(* Logix 5000 project; controller Test vendor 1 type 14 code 92 rev 33.11; software revision 33.00; part 4 of 4 *)
(* tags used below, declared in another part *)
   WLS : Banner_WLS_v4;
   Port_Data : Banner_IOL_Port_v4;
   Port : INT;   // Port Number that device is plugged into.
   Local_Control : DINT;
   Command_Being_Processed : BOOL;
   Update_Archive : BOOL;
   Index_Write_Inprocess : DINT;
   Inprocess_Index : DINT;
   GW_Index : DINT;
(* Banner_WLS_Param_v4, continued *)

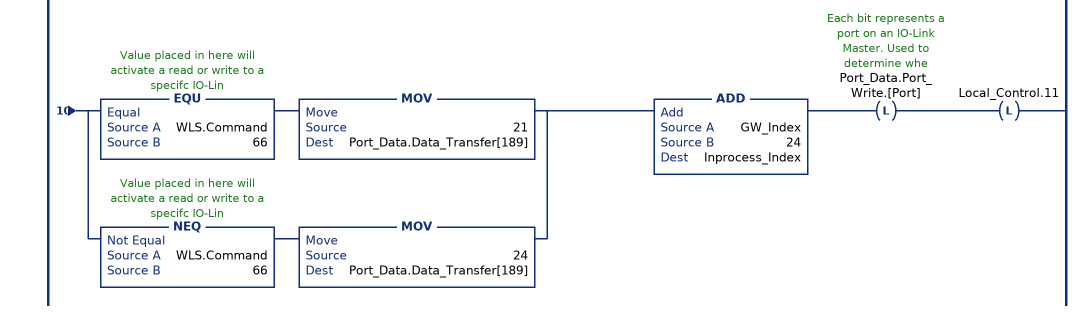
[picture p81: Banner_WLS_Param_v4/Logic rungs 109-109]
   // *****************************************************************************************************************************************************************************
   // Section of AOI that controls writing of the Gauge Mode Center Settings parameters (index 86), Gauge Mode Threshold 1 & 2 Settings (Index 87 &88).
   // *****************************************************************************************************************************************************************************
   109: XIO(Command_Being_Processed)XIO(Local_Control.11)GEQ(WLS.Command,66)LEQ(WLS.Command,68)SUB(WLS.Command,66,GW_Index)OTL(Command_Being_Processed)BTD(WLS.Write.G_Config.CC[GW_Index].Back_CC.Direction,0,Port_Data.Data_Transfer[0],0,8)BTD(WLS.Write.G_Config.CC[GW_Index].Back_CC.Percent_Width_C1,0,Port_Data.Data_Transfer[1],0,8)BTD(WLS.Write.G_Config.CC[GW_Index].Back_CC.ScrollBounce,0,Port_Data.Data_Transfer[2],0,8)BTD(WLS.Write.G_Config.CC[GW_Index].Back_CC.Color_2_Intensity,0,Port_Data.Data_Transfer[3],0,8)BTD(WLS.Write.G_Config.CC[GW_Index].Back_CC.Color_2,0,Port_Data.Data_Transfer[4],0,8)BTD(WLS.Write.G_Config.CC[GW_Index].Back_CC.Pulse_Pattern,0,Port_Data.Data_Transfer[5],0,8)BTD(WLS.Write.G_Config.CC[GW_Index].Back_CC.Speed,0,Port_Data.Data_Transfer[6],0,8)BTD(WLS.Write.G_Config.CC[GW_Index].Back_CC.Color_1_Intensity,0,Port_Data.Data_Transfer[7],0,8)BTD(WLS.Write.G_Config.CC[GW_Index].Back_CC.Color_1,0,Port_Data.Data_Transfer[8],0,8)BTD(WLS.Write.G_Config.CC[GW_Index].Back_CC.Animation,0,Port_Data.Data_Transfer[9],0,8)BTD(WLS.Write.G_Config.CC[GW_Index].Main_CC.Direction,0,Port_Data.Data_Transfer[10],0,8)BTD(WLS.Write.G_Config.CC[GW_Index].Main_CC.Percent_Width_C1,0,Port_Data.Data_Transfer[11],0,8)BTD(WLS.Write.G_Config.CC[GW_Index].Main_CC.ScrollBounce,0,Port_Data.Data_Transfer[12],0,8)BTD(WLS.Write.G_Config.CC[GW_Index].Main_CC.Color_2_Intensity,0,Port_Data.Data_Transfer[13],0,8)BTD(WLS.Write.G_Config.CC[GW_Index].Main_CC.Color_2,0,Port_Data.Data_Transfer[14],0,8)BTD(WLS.Write.G_Config.CC[GW_Index].Main_CC.Pulse_Pattern,0,Port_Data.Data_Transfer[15],0,8)BTD(WLS.Write.G_Config.CC[GW_Index].Main_CC.Speed,0,Port_Data.Data_Transfer[16],0,8)BTD(WLS.Write.G_Config.CC[GW_Index].Main_CC.Color_1_Intensity,0,Port_Data.Data_Transfer[17],0,8)BTD(WLS.Write.G_Config.CC[GW_Index].Main_CC.Color_1,0,Port_Data.Data_Transfer[18],0,8)BTD(WLS.Write.G_Config.CC[GW_Index].Main_CC.Animation,0,Port_Data.Data_Transfer[19],0,8)BTD(WLS.Write.G_Config.CC[GW_Index].Percent_Width_of_Main_Segment,0,Port_Data.Data_Transfer[20],0,8)BTD(WLS.Write.G_Config.CC[GW_Index].Threshold_Comparison,0,Port_Data.Data_Transfer[21],0,8)BTD(WLS.Write.G_Config.CC[GW_Index].Threshold_Value_Percent,0,Port_Data.Data_Transfer[22],0,8)BTD(WLS.Write.G_Config.CC[GW_Index].Threshold_Enable,0,Port_Data.Data_Transfer[23],0,8)MOV(Port,Port_Data.Data_Transfer[185])MOV(0,Port_Data.Data_Transfer[187])ADD(WLS.Command,20,Port_Data.Data_Transfer[188])[EQU(WLS.Command,66) MOV(21,Port_Data.Data_Transfer[189]) ,NEQ(WLS.Command,66) MOV(24,Port_Data.Data_Transfer[189]) ]ADD(GW_Index,24,Inprocess_Index)OTL(Port_Data.Port_Write.[Port])OTL(Local_Control.11);
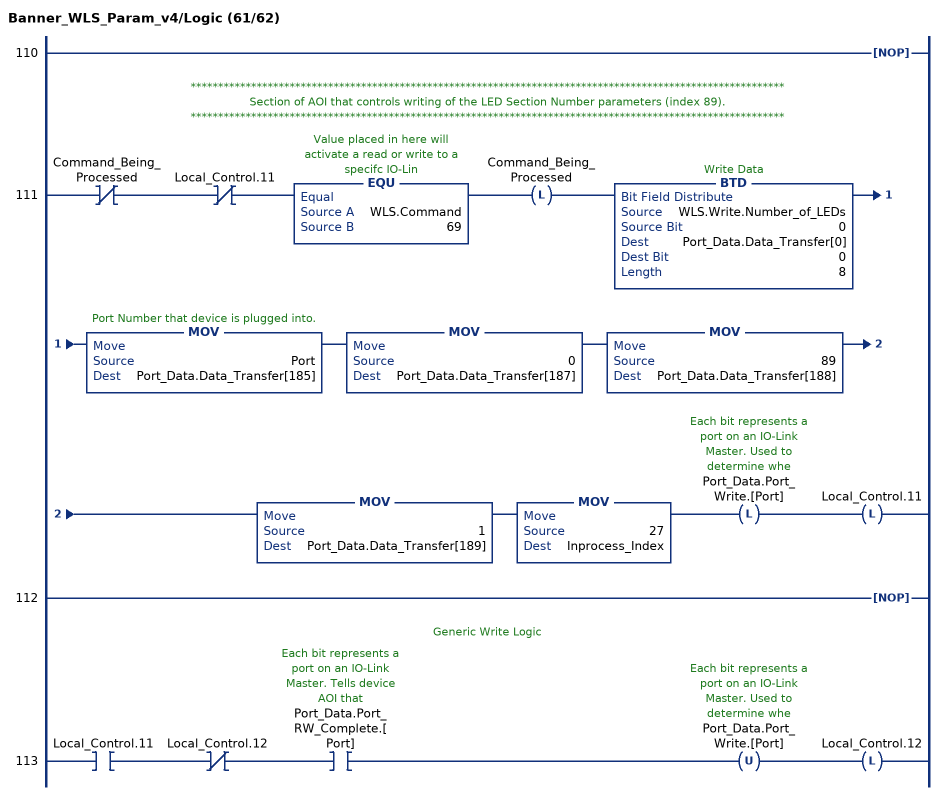
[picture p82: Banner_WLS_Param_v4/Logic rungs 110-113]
   110: NOP();
   // ************************************************************************************************************
   // Section of AOI that controls writing of the LED Section Number parameters (index 89).
   // ************************************************************************************************************
   111: XIO(Command_Being_Processed)XIO(Local_Control.11)EQU(WLS.Command,69)OTL(Command_Being_Processed)BTD(WLS.Write.Number_of_LEDs,0,Port_Data.Data_Transfer[0],0,8)MOV(Port,Port_Data.Data_Transfer[185])MOV(0,Port_Data.Data_Transfer[187])MOV(89,Port_Data.Data_Transfer[188])MOV(1,Port_Data.Data_Transfer[189])MOV(27,Inprocess_Index)OTL(Port_Data.Port_Write.[Port])OTL(Local_Control.11);
   112: NOP();
   // Generic Write Logic
   113: XIC(Local_Control.11)XIO(Local_Control.12)XIC(Port_Data.Port_RW_Complete.[Port])OTU(Port_Data.Port_Write.[Port])OTL(Local_Control.12);
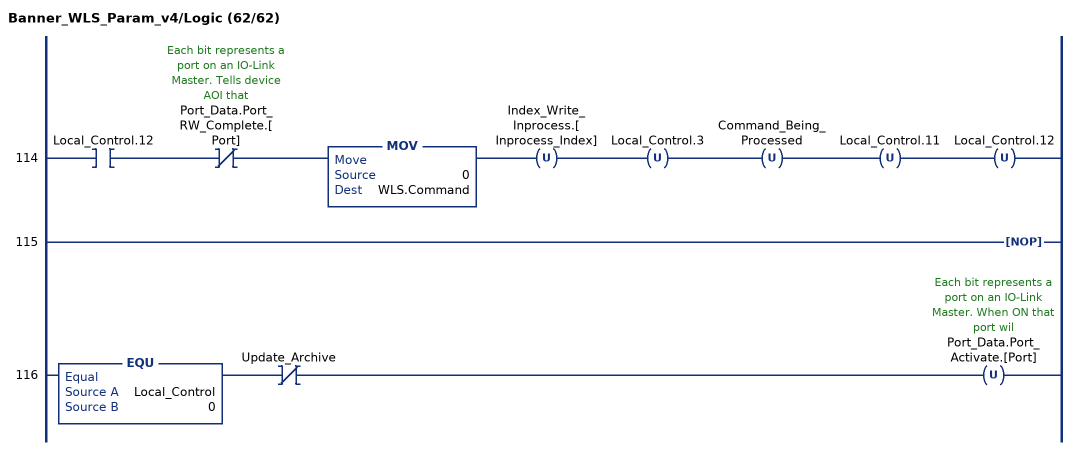
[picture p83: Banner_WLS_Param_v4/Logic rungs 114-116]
   114: XIC(Local_Control.12)XIO(Port_Data.Port_RW_Complete.[Port])MOV(0,WLS.Command)OTU(Index_Write_Inprocess.[Inprocess_Index])OTU(Local_Control.3)OTU(Command_Being_Processed)OTU(Local_Control.11)OTU(Local_Control.12);
   115: NOP();
   116: EQU(Local_Control,0)XIO(Update_Archive)OTU(Port_Data.Port_Activate.[Port]);
END_ROUTINE
END_ADD_ON_INSTRUCTION

VAR_GLOBAL   (* controller tags *)
   Block : BOOL;
   IOL_Reset : BOOL;
   IOLM1 : Banner_IOLM_v4;
   IOLM1_Status : Banner_DXMR90_IOLM_v4;
   WLF_IOLM1_01 : Banner_WLS_v4;
   WLF_IOLM1_01_PD : Banner_WLF_LC25C_PDIO_v4;
   WLF_IOLM1_01_PD_Status : Banner_WLF_LC25C_PD_v4;
   WLF_IOLM1_01_Status : Banner_WLS_Param_v4;
END_VAR

PROGRAM MainProgram   (* main routine MainRoutine *)

ROUTINE MainRoutine   (* ladder *)
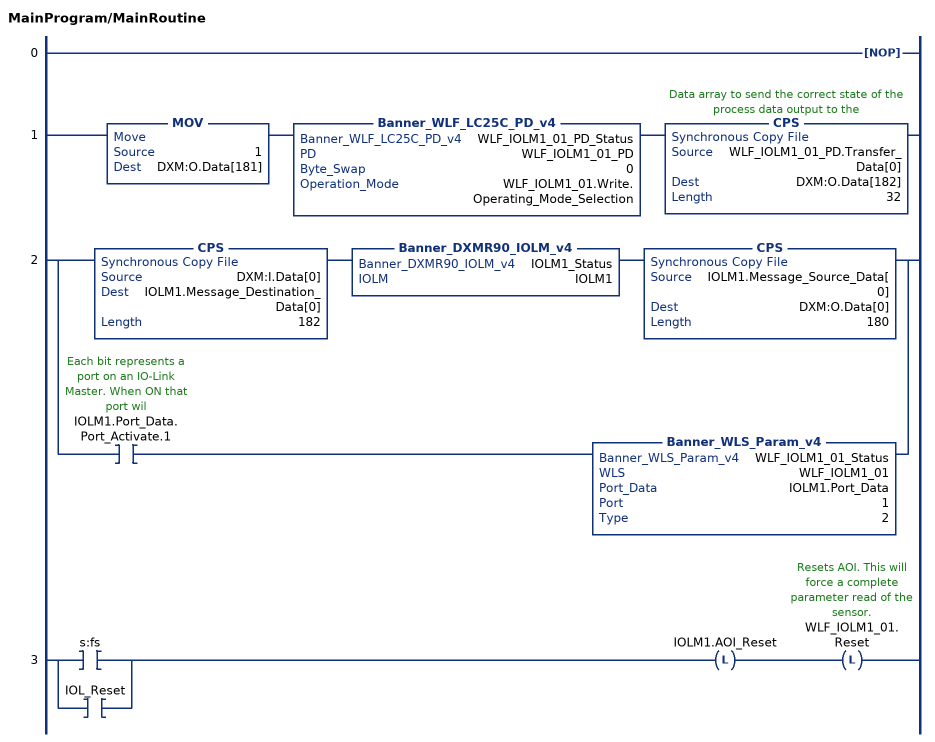
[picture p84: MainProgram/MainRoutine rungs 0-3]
   0: NOP();
   1: MOV(1,DXM:O.Data[181])Banner_WLF_LC25C_PD_v4(WLF_IOLM1_01_PD_Status,WLF_IOLM1_01_PD,0,WLF_IOLM1_01.Write.Operating_Mode_Selection)CPS(WLF_IOLM1_01_PD.Transfer_Data[0],DXM:O.Data[182],32);
   2: [CPS(DXM:I.Data[0],IOLM1.Message_Destination_Data[0],182) Banner_DXMR90_IOLM_v4(IOLM1_Status,IOLM1) CPS(IOLM1.Message_Source_Data[0],DXM:O.Data[0],180) ,XIC(IOLM1.Port_Data.Port_Activate.1) Banner_WLS_Param_v4(WLF_IOLM1_01_Status,WLF_IOLM1_01,IOLM1.Port_Data,1,2) ];
   3: [XIC(s:fs) ,XIC(IOL_Reset) ]OTL(IOLM1.AOI_Reset)OTL(WLF_IOLM1_01.Reset);
END_ROUTINE
END_PROGRAM
